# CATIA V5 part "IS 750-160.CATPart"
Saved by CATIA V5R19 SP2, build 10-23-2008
Part number: IS 750-160
Bounding box of the stored display mesh (mm): x -24.865 to 24.865, y -24.997 to 24.997, z 0 to 415
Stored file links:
  C:\Users\Bora\Desktop\3D Katı model\IS serisi\IS 750\IS 750-160.CATPart
  C:\Program Files\Dassault Systemes\B19\intel_a\reffiles\standard\MetricThickPitch.txt
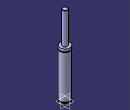
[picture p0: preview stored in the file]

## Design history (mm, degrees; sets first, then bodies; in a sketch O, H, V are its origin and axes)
Body1 (main body)
  Sketch1 on yz-plane, origin (0, 0, 0), H (0, 1, 0), V (0, 0, 1)
    point P1 (25, 239.5)
    point P2 (25, 235.5)
    point P5 (12.5, 414)
    point P7 (12.5, 414)
    point P12 (25, 235.5)
    point P13 (25, 239.5)
    arc A1 centre (25, 237.5) radius 2 from (25, 239.5) to (25, 235.5) ccw
    line L1 (25, 0) -> (25, 8)
    line L2 (12.5, 414) -> (12.5, 252)
    arc A2 centre (11.5, 414) radius 1 from (12.5, 414) to (11.5, 415) ccw
    line L3 (21.5, 13) -> (21.5, 8)
    line L4 (25, 13) -> (25, 235.5)
    line L5 (25, 239.5) -> (25, 252)
    line L6 (11.5, 415) -> (0, 415)
    point P15 (0, 415)
    line L7 (12.5, 252) -> (25, 252)
    line L8 (0, 0) -> (25, 0)
    line L9 (21.5, 8) -> (25, 8)
    line L10 (21.5, 13) -> (25, 13)
    coincidence: P15 V, P1 P13, P2 P12, P5 P7
    tangency: L6 A2
    horizontal: L7 H, L8 H, L9 H, L10 H
  Shaft1: profile Sketch1, axis Sketch1.V, angle 360
  Sketch2 on face of Shaft1 from Sketch1.L8, origin (0, 0, 0), H (1, 0, 0), V (0, -1, 0)
    point P1 (10, 0)
    distance P1 V = 10
  Hole1: placed by Sketch2, at (10, 0, 0) direction (0, 0, 1), diameter 6.647, depth 13, threaded "M8", thread diameter 8, thread depth 13, pitch 1.25
  Sketch3 on face of Shaft1 from Sketch1.L8, origin (0, 0, 0), H (1, 0, 0), V (0, -1, 0)
    point P1 (-10, 0)
    distance P1 V = 10
  Hole2: placed by Sketch3, at (-10, 0, 0) direction (0, 0, 1), diameter 6.647, depth 13, threaded "M8", thread diameter 8, thread depth 13, pitch 1.25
